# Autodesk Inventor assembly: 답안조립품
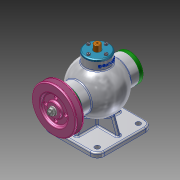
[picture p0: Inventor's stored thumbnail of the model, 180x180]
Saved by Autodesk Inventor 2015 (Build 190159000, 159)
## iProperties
Created: 2025-08
Part Number: 답안조립품
Document SubType Name: Assembly
Designer: user
Author: user
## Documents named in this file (15)
- C:\Users\user\Desktop\750808V1006\답안조립품.iam
- C:\Users\user\Desktop\750808V1006\본체.ipt
- C:\Users\user\Desktop\750808V1006\가져온 구성요소\V-벨트풀리\V-벨트풀리.ipt
- C:\Users\user\Desktop\750808V1006\가져온 구성요소\너트 M8\너트 M8.ipt
- C:\Users\user\Desktop\750808V1006\가져온 구성요소\뒤커버\뒤커버.ipt
- C:\Users\user\Desktop\750808V1006\가져온 구성요소\베어링- 6202\베어링- 6202.ipt
- C:\Users\user\Desktop\750808V1006\가져온 구성요소\볼트 M4 x 12\볼트 M4 x 12.ipt
- C:\Users\user\Desktop\750808V1006\가져온 구성요소\볼트 M4 x 16\볼트 M4 x 16.ipt
- C:\Users\user\Desktop\750808V1006\가져온 구성요소\상부커버\상부커버.ipt
- C:\Users\user\Desktop\750808V1006\가져온 구성요소\슬라이드\슬라이드.ipt
- C:\Users\user\Desktop\750808V1006\가져온 구성요소\앞커버\앞커버.ipt
- C:\Users\user\Desktop\750808V1006\가져온 구성요소\오일실 15 30 7\오일실 15 30 7.ipt
- C:\Users\user\Desktop\750808V1006\가져온 구성요소\칼라\칼라.ipt
- C:\Users\user\Desktop\750808V1006\가져온 구성요소\키 4 x 4 x 12\키 4 x 4 x 12.ipt
- C:\Users\user\Desktop\750808V1006\가져온 구성요소\편심축\편심축.ipt
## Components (1 placed, 1 different names)
1. V-벨트풀리:1
